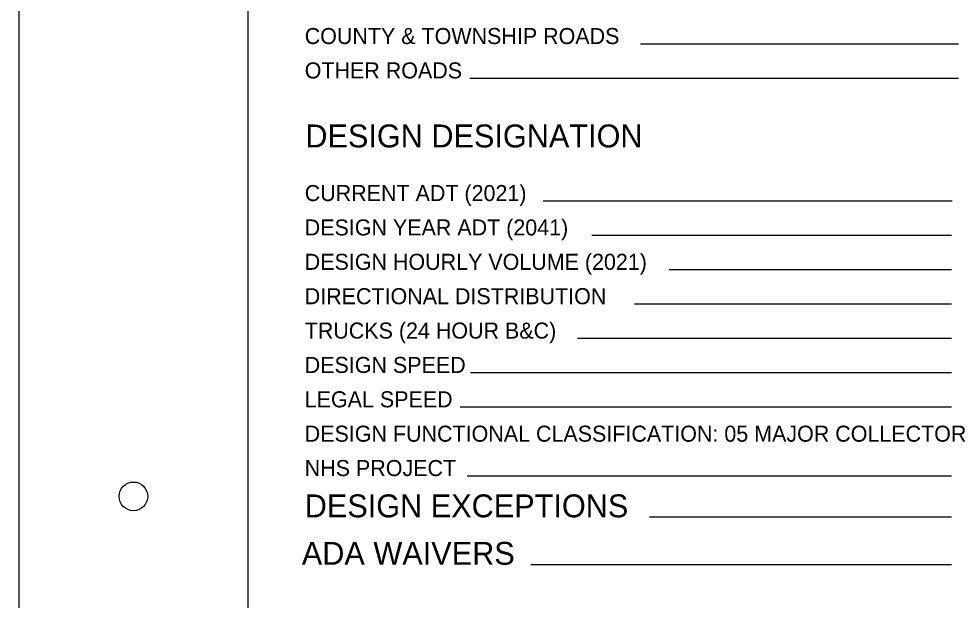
# Model space of a CAD drawing. Extents: x 1862092.2 to 1862141.4, y 420599.8 to 420643.6.
# Drawn here: x 1862096.98 to 1862105.2, y 420606.46 to 420611.53 of the extents above; entities that cross this region are included whole.
import ezdxf

# ---------------------------------------------------------------- set-up
doc = ezdxf.new("R2010")
doc.units = 0
for name, color, linetype in [('SH_Border', 7, 'Continuous'), ('SH_Cut_Line', 7, 'Continuous'), ('SH_Data', 7, 'Continuous')]:
    doc.layers.add(name, color=color, linetype=linetype)

msp = doc.modelspace()

# ---------------------------------------------------------------- linework, layer by layer
at = {"layer": 'SH_Border'}
msp.add_lwpolyline([(1862098.979, 420622.1158), (1862130.479, 420622.1158), (1862130.479, 420601.1158), (1862098.979, 420601.1158)], close=True, dxfattribs=at)
msp.add_circle((1862097.979, 420607.3658), 0.125, dxfattribs=at)
at = {"layer": 'SH_Cut_Line'}
msp.add_lwpolyline([(1862096.979, 420600.6158), (1862130.979, 420600.6158), (1862130.979, 420622.6158), (1862096.979, 420622.6158)], close=True, dxfattribs=at)
at = {"layer": 'SH_Data'}
for p, q in [((1862105.179, 420611.3133), (1862102.403, 420611.3133)), ((1862105.179, 420611.0133), (1862100.9138, 420611.0133)), ((1862105.1214, 420609.9428), (1862101.5527, 420609.9428)), ((1862105.1158, 420609.6428), (1862101.9777, 420609.6428)), ((1862105.1158, 420609.3428), (1862102.6548, 420609.3428)), ((1862105.1158, 420609.0428), (1862102.3501, 420609.0428)), ((1862105.1158, 420608.7428), (1862101.8536, 420608.7428)), ((1862105.1158, 420608.4428), (1862100.9207, 420608.4428)), ((1862105.1158, 420608.1428), (1862100.8304, 420608.1428)), ((1862105.1158, 420607.5428), (1862100.8906, 420607.5428)), ((1862105.1158, 420607.1828), (1862102.4818, 420607.1828)), ((1862105.1158, 420606.7686), (1862101.4458, 420606.7686))]:
    msp.add_line(p, q, dxfattribs=at)

# ---------------------------------------------------------------- texts
for s, height, p in [('COUNTY & TOWNSHIP ROADS', 0.14, (1862099.4734, 420611.3133)), ('OTHER ROADS', 0.14, (1862099.4734, 420611.0133)), ('DESIGN DESIGNATION', 0.2, (1862099.479, 420610.4113)), ('CURRENT ADT (2021)', 0.14, (1862099.4734, 420609.9428)), ('DESIGN YEAR ADT (2041)', 0.14, (1862099.4734, 420609.6428)), ('DESIGN HOURLY VOLUME (2021)', 0.14, (1862099.4734, 420609.3428)), ('DIRECTIONAL DISTRIBUTION', 0.14, (1862099.4734, 420609.0428)), ('TRUCKS (24 HOUR B&C)', 0.14, (1862099.4734, 420608.7428)), ('DESIGN SPEED', 0.14, (1862099.4734, 420608.4428)), ('LEGAL SPEED', 0.14, (1862099.4734, 420608.1428)), ('DESIGN FUNCTIONAL CLASSIFICATION: 05 MAJOR COLLECTOR', 0.14, (1862099.4734, 420607.8428)), ('NHS PROJECT', 0.14, (1862099.4734, 420607.5428)), ('DESIGN EXCEPTIONS', 0.2, (1862099.4734, 420607.1828)), ('ADA WAIVERS', 0.2, (1862099.4481, 420606.7686))]:
    msp.add_text(s, height=height, dxfattribs=at).set_placement(p)

doc.saveas('drawing.dxf')
